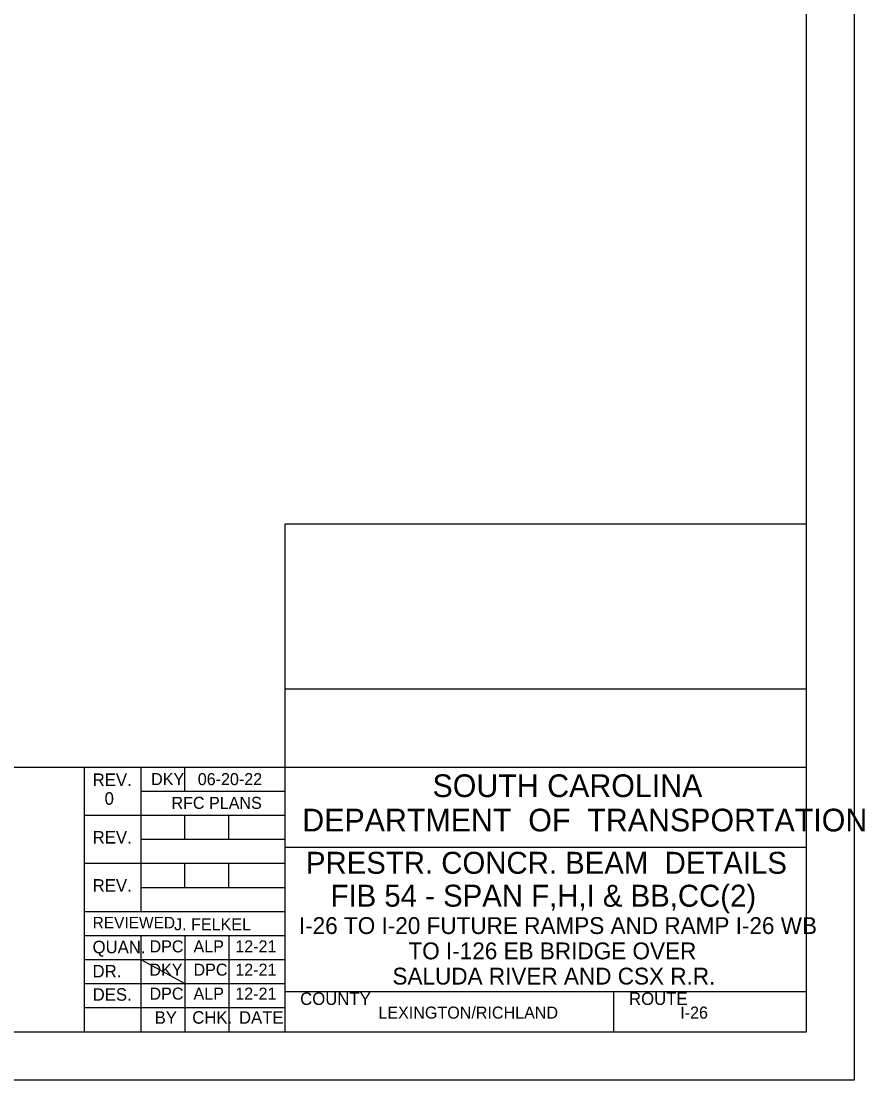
# Model space of a CAD drawing. Extents: x -55.6 to -19.5, y -100.1 to -78.1.
# Drawn here: x -28.24 to -19.48, y -100.12 to -89.12 of the extents above; entities that cross this region are included whole.
import ezdxf

# ---------------------------------------------------------------- set-up
doc = ezdxf.new("R2010")
doc.units = 0
for name, color, linetype in [('BR_BORDER LINES', 7, 'Continuous'), ('BR_TEXT', 7, 'Continuous'), ('Level 31', 7, 'Continuous')]:
    doc.layers.add(name, color=color, linetype=linetype)

msp = doc.modelspace()

# ---------------------------------------------------------------- linework, layer by layer
at = {"layer": 'BR_BORDER LINES'}
for p, q in [((-20.084, -99.621), (-20.084, -78.621)), ((-25.501, -99.621), (-25.501, -94.345)), ((-25.501, -94.345), (-20.084, -94.345)), ((-25.501, -96.059), (-20.084, -96.059)), ((-32.95, -96.871), (-27.584, -96.871)), ((-27.584, -99.621), (-27.584, -96.871)), ((-27.584, -96.871), (-20.084, -96.871)), ((-27.001, -96.871), (-27.001, -98.371)), ((-26.543, -97.121), (-26.543, -96.871)), ((-27.001, -97.121), (-25.501, -97.121)), ((-27.584, -97.371), (-25.501, -97.371)), ((-26.543, -97.621), (-26.543, -97.371)), ((-26.084, -97.621), (-26.084, -97.371)), ((-27.001, -97.621), (-25.501, -97.621)), ((-25.501, -97.704), (-25.501, -97.704)), ((-25.501, -97.704), (-20.084, -97.704)), ((-27.584, -97.871), (-25.501, -97.871)), ((-26.543, -98.121), (-26.543, -97.871)), ((-26.084, -98.121), (-26.084, -97.871)), ((-27.001, -98.121), (-25.501, -98.121)), ((-27.584, -98.371), (-25.501, -98.371)), ((-27.584, -98.621), (-25.501, -98.621)), ((-27.001, -98.621), (-27.001, -99.621)), ((-26.543, -98.621), (-26.543, -99.621)), ((-26.084, -98.621), (-26.084, -99.621)), ((-27.584, -98.871), (-25.501, -98.871)), ((-27.584, -99.121), (-25.501, -99.121)), ((-25.501, -99.204), (-20.084, -99.204)), ((-25.403, -99.204), (-20.084, -99.204)), ((-22.084, -99.621), (-22.084, -99.204)), ((-27.584, -99.371), (-25.501, -99.371)), ((-53.75, -99.621), (-20.084, -99.621))]:
    msp.add_line(p, q, dxfattribs=at)
at = {"layer": 'Level 31'}
for p, q in [((-22.792, -98.145), (-22.792, -98.145)), ((-27.001, -98.871), (-26.543, -99.121))]:
    msp.add_line(p, q, dxfattribs=at)
msp.add_lwpolyline([(-55.583, -100.121), (-19.583, -100.121), (-19.583, -78.121), (-55.583, -78.121)], close=True, dxfattribs=at)

# ---------------------------------------------------------------- texts
at = {"layer": 'BR_TEXT'}
for s, height, p in [('REV.', 0.13, (-27.5, -97.068)), ('DKY', 0.125, (-26.893, -97.059)), ('06-20-22', 0.125, (-26.408, -97.059)), ('SOUTH CAROLINA', 0.23587, (-23.969, -97.183)), ('0', 0.13, (-27.376, -97.263)), ('RFC PLANS', 0.125, (-26.681, -97.306)), ('DEPARTMENT  OF  TRANSPORTATION', 0.23587, (-25.322, -97.54)), ('REV.', 0.13, (-27.5, -97.666)), ('PRESTR. CONCR. BEAM  DETAILS', 0.228, (-25.284, -97.98)), ('REV.', 0.13, (-27.5, -98.166)), ('FIB 54 - SPAN F,H,I & BB,CC(2)', 0.228, (-25.028, -98.322)), ('REVIEWED', 0.12, (-27.5, -98.548)), ('J. FELKEL', 0.125, (-26.654, -98.567)), ('I-26 TO I-20 FUTURE RAMPS AND RAMP I-26 WB', 0.175, (-25.357, -98.606)), ('QUAN.', 0.13, (-27.501, -98.806)), ('DPC', 0.125, (-26.909, -98.797)), ('ALP', 0.125, (-26.452, -98.797)), ('12-21', 0.125, (-26.018, -98.797)), ('TO I-126 EB BRIDGE OVER', 0.175, (-24.219, -98.869)), ('DR.', 0.13, (-27.501, -99.057)), ('DKY', 0.125, (-26.91, -99.039)), ('DPC', 0.125, (-26.452, -99.039)), ('12-21', 0.125, (-26.018, -99.039)), ('SALUDA RIVER AND CSX R.R.', 0.175, (-24.385, -99.131)), ('DES.', 0.13, (-27.5, -99.299)), ('DPC', 0.125, (-26.909, -99.288)), ('ALP', 0.125, (-26.452, -99.288)), ('12-21', 0.125, (-26.018, -99.288)), ('COUNTY', 0.13, (-25.344, -99.343)), ('ROUTE', 0.13, (-21.927, -99.343)), ('BY', 0.13, (-26.856, -99.539)), ('CHK.', 0.13, (-26.465, -99.538)), ('DATE', 0.13, (-25.98, -99.538)), ('LEXINGTON/RICHLAND', 0.12499, (-24.531, -99.485)), ('I-26', 0.125, (-21.395, -99.485))]:
    msp.add_text(s, height=height, dxfattribs=at).set_placement(p)

doc.saveas('drawing.dxf')
